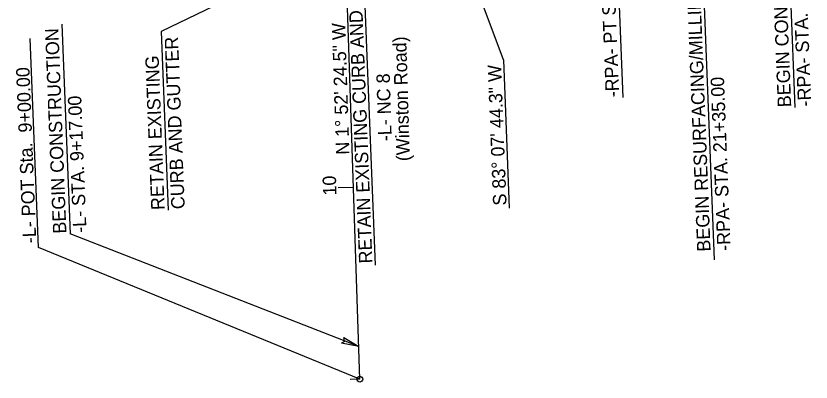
# Model space of a CAD drawing. Extents: x 1627861 to 1629601, y 761281 to 766239.
# Drawn here: x 1628322.6 to 1628737.3, y 761374.2 to 761565 of the extents above; entities that cross this region are included whole.
import ezdxf

# ---------------------------------------------------------------- set-up
doc = ezdxf.new("R2010")
doc.units = 0
for name, color, linetype in [('Cogo Default Point CELL', 7, 'Continuous'), ('Exist Other Culture Sign Leader', 7, 'Continuous'), ('Exist Property Tie Line Leader', 7, 'Continuous'), ('Exist Property Tie Line Text', 7, 'Continuous'), ('Exist Right of Way Line Leader', 7, 'Continuous'), ('Exist Utilities Gas Meter CELL', 7, 'Continuous'), ('Exist Utilities Gas Meter Cogo Number', 7, 'Continuous'), ('Exist Utilities Power UG Cable SUE LOS B Cogo Point CELL', 7, 'Continuous'), ('Exist Utilities Water Meter Cogo Elevation', 7, 'Continuous'), ('Scratch_Level_0', 7, 'Continuous')]:
    doc.layers.add(name, color=color, linetype=linetype)

msp = doc.modelspace()

# ---------------------------------------------------------------- linework, layer by layer
at = {"layer": 'Exist Property Tie Line Text'}
msp.add_line((1628501.93, 761375.68), (1628496.94, 761375.52), dxfattribs=at)
at = {"layer": 'Exist Right of Way Line Leader'}
for p, q in [((1628576.79, 761542.18), (1628516.43, 761703.55)), ((1628634.23, 761646.28), (1628639.11, 761522.47)), ((1628334.32, 761444.35), (1628330.03, 761553.23)), ((1628576.79, 761542.18), (1628579.83, 761464.87)), ((1628501.93, 761375.68), (1628334.32, 761444.35))]:
    msp.add_line(p, q, dxfattribs=at)
msp.add_circle((1628501.93, 761375.68), 1.5, dxfattribs=at)
at = {"layer": 'Exist Utilities Gas Meter CELL'}
msp.add_line((1628501.93, 761375.68), (1628492.12, 761675.69), dxfattribs=at)
at = {"layer": 'Exist Utilities Gas Meter Cogo Number'}
msp.add_lwpolyline([(1628493.56, 761397.39), (1628501.38, 761392.67), (1628492.37, 761394.47), (1628494.02, 761395.55)], close=True, dxfattribs=at)
at = {"layer": 'Exist Utilities Water Meter Cogo Elevation'}
msp.add_line((1628498.66, 761475.63), (1628490.67, 761475.37), dxfattribs=at)
at = {"layer": 'Scratch_Level_0'}
for p, q in [((1628724.58, 761626.53), (1628728.88, 761517.35)), ((1628502.85, 761612.9), (1628509.86, 761435.2)), ((1628454.97, 761584.36), (1628398.39, 761556.83)), ((1628681.22, 761576.16), (1628686.67, 761437.91)), ((1628346.53, 761560.66), (1628350.84, 761451.48)), ((1628398.39, 761556.83), (1628402.06, 761463.79)), ((1628501.38, 761392.67), (1628350.84, 761451.48))]:
    msp.add_line(p, q, dxfattribs=at)

# ---------------------------------------------------------------- texts
at = {"layer": 'Cogo Default Point CELL'}
for s, rotation, p in [('N 1%%d 52\' 24.5" W', 91.8735, (1628496.56, 761492.78)), ('S 83%%d 07\' 44.3" W', 92.2582, (1628578.5, 761466.3))]:
    msp.add_text(s, height=7, rotation=rotation, dxfattribs=at).set_placement(p)
at = {"layer": 'Exist Other Culture Sign Leader'}
for s, rotation, p in [('BEGIN CONSTRUCTION', 92.2582, (1628726.97, 761517.55)), ('-RPA- STA. 19+90.00', 92.2582, (1628737.46, 761517.96)), ('BEGIN RESURFACING/MILLING', 92.2582, (1628684.92, 761442.28)), ('BEGIN CONSTRUCTION', 92.2582, (1628348.93, 761451.68)), ('(Winston Road)', 91.7316, (1628528.09, 761489.43)), ('-L- NC 8', 91.7316, (1628518.6, 761499.8)), ('-RPA- STA. 21+35.00', 92.2582, (1628695.41, 761442.7)), ('-L- STA. 9+17.00', 92.2582, (1628359.42, 761452.09))]:
    msp.add_text(s, height=7, rotation=rotation, dxfattribs=at).set_placement(p)
at = {"layer": 'Exist Property Tie Line Leader'}
msp.add_text('10', height=7, rotation=91.8735, dxfattribs=at).set_placement((1628489.8, 761471.48))
at = {"layer": 'Exist Right of Way Line Leader'}
for s, p in [('-RPA- PT Sta.  20+63.28', (1628637.22, 761522.71)), ('-L- POT Sta.  9+00.00', (1628333.22, 761446.68))]:
    msp.add_text(s, height=7, rotation=92.2582, dxfattribs=at).set_placement(p)
at = {"layer": 'Exist Utilities Power UG Cable SUE LOS B Cogo Point CELL'}
for s, p in [('RETAIN EXISTING CURB AND GUTTER', (1628508.55, 761436.14)), ('CURB AND GUTTER', (1628410.66, 761464.42)), ('RETAIN EXISTING', (1628400.17, 761464))]:
    msp.add_text(s, height=7, rotation=92.2582, dxfattribs=at).set_placement(p)

doc.saveas('drawing.dxf')
